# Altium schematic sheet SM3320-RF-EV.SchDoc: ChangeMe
size 469 x 254 mm; Date: Not shown in title block; ApprovedBy: Not shown in title block; CheckedBy: Not shown in title block; Author: Not shown in title block; CompanyName: Not shown in title block; DrawnBy: Not shown in title block; Engineer: Not shown in title block; Organization: Not shown in title block; Address1: Not shown in title block; Address2: Not shown in title block; Address3: Not shown in title block; Address4: Not shown in title block; DocumentNumber: 1; Revision: Use project parameter SCH_Rev; SheetNumber: 1; SheetTotal: 1; PageSetup: Record=PageOptions|CenterHorizontal=True|CenterVertical=True|PrintScale=0.85|XCorrection=0.00|YCorrection=0.00|PrintKind=2|BorderSize=5000000|LeftOffset=0|BottomOffset=0|Orientation=2|PaperLength=1000|PaperWidth=1000|Scale=100|PaperSource=15|PrintQuality=600|MediaType=1|DitherType=10|PaperKind=11x17|PrintScaleMode=0
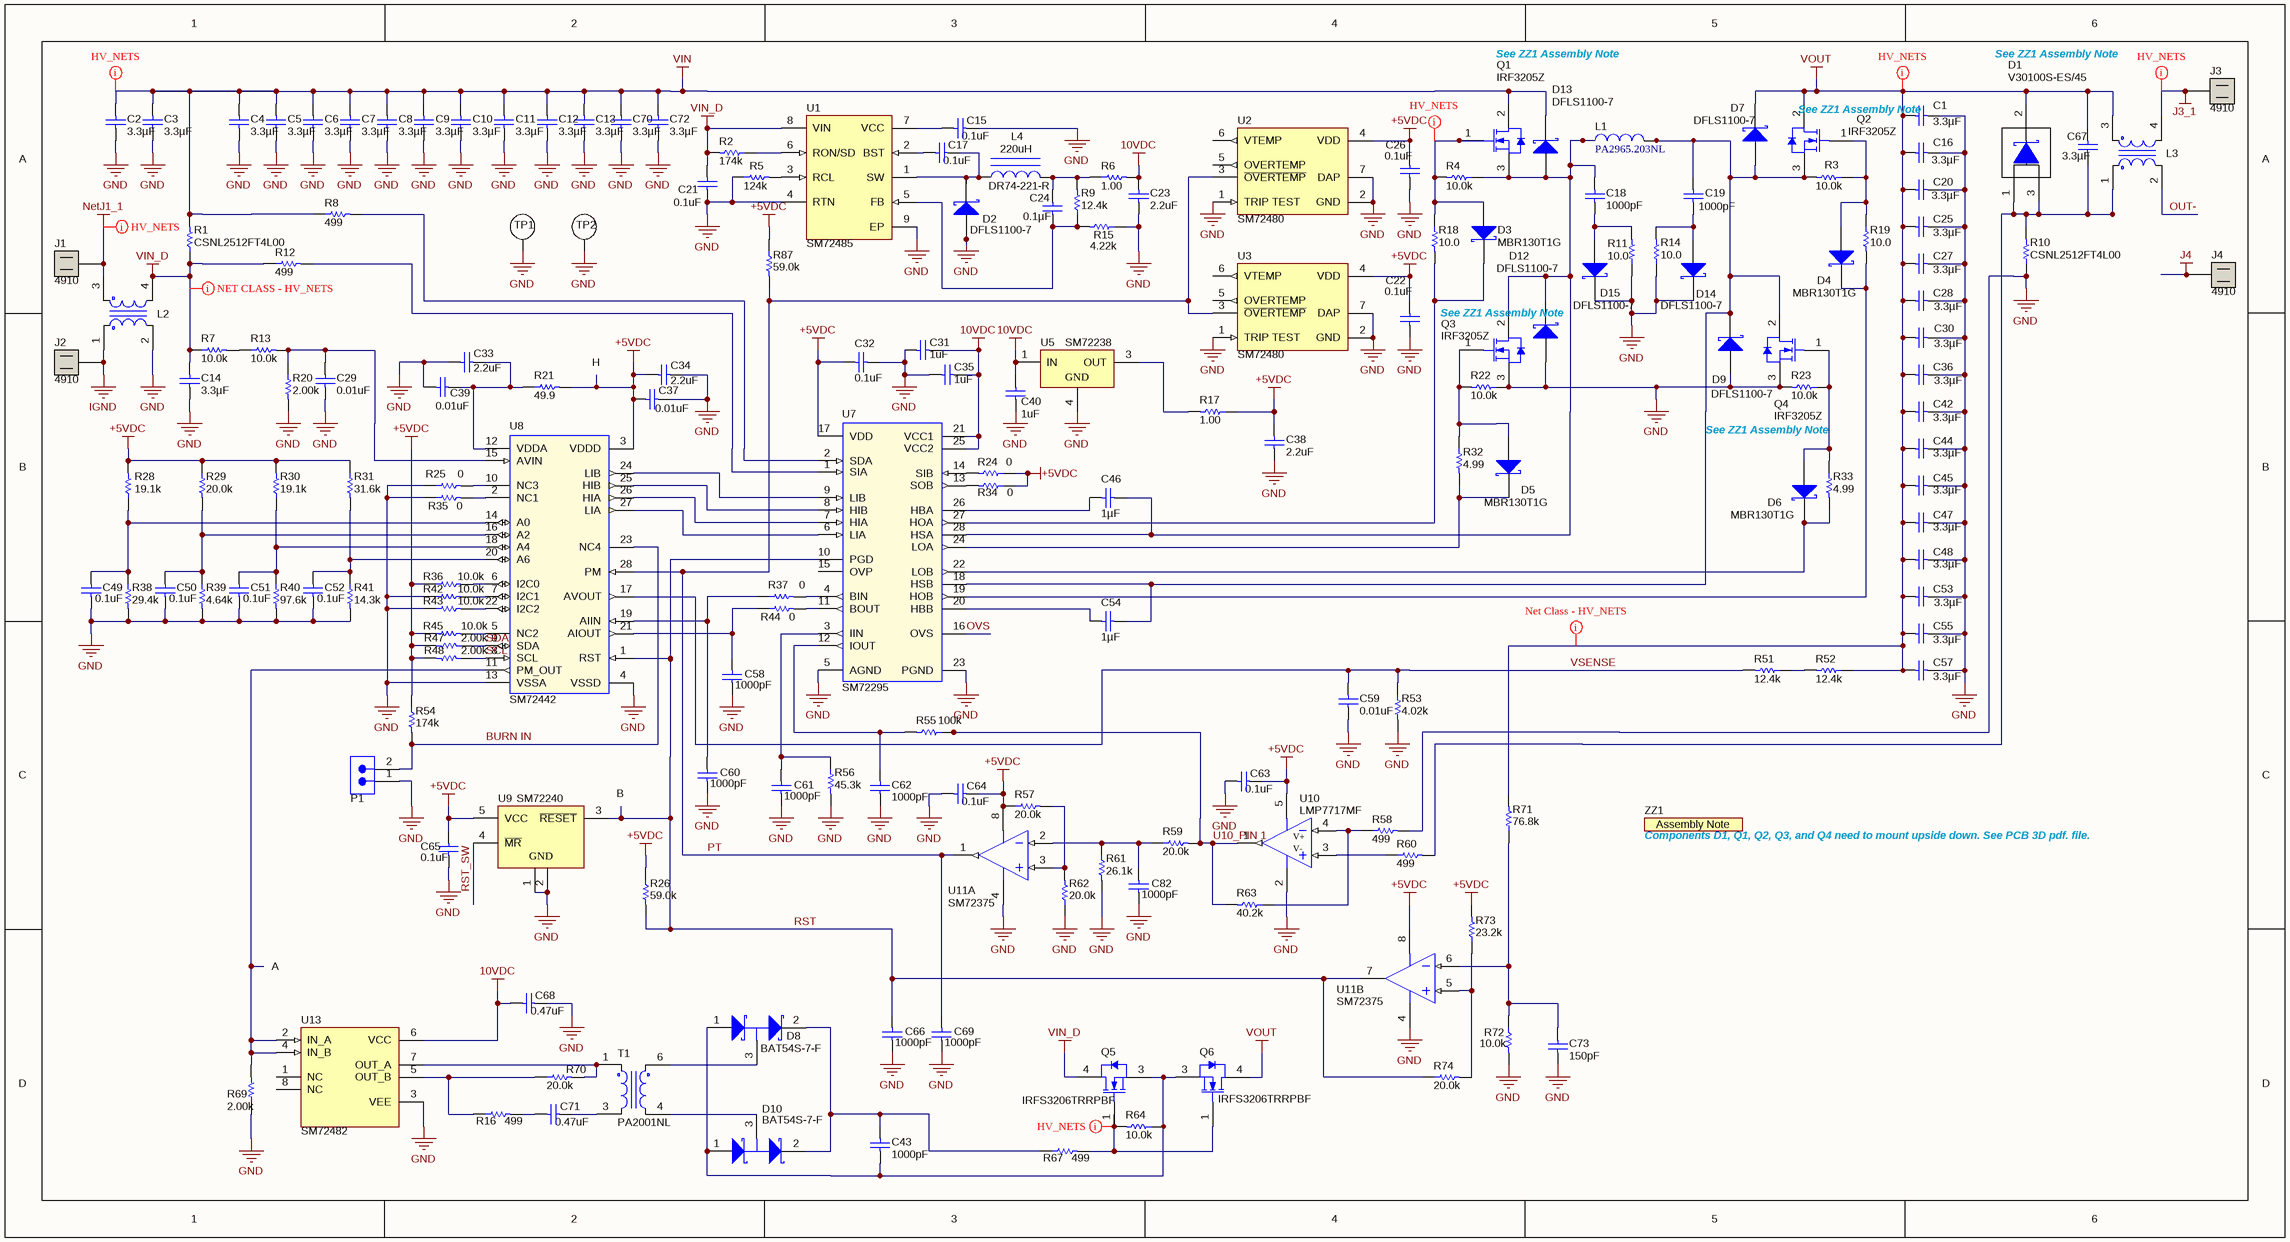
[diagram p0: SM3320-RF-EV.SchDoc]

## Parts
C1  ValueDisplayed: 3.3µF  [1210]  (hidden comment: C3225X7R1H335M)
C2  ValueDisplayed: 3.3µF  [1210]  (hidden comment: C3225X7R1H335M)
C3  ValueDisplayed: 3.3µF  [1210]  (hidden comment: C3225X7R1H335M)
C4  ValueDisplayed: 3.3µF  [1210]  (hidden comment: C3225X7R1H335M)
C5  ValueDisplayed: 3.3µF  [1210]  (hidden comment: C3225X7R1H335M)
C6  ValueDisplayed: 3.3µF  [1210]  (hidden comment: C3225X7R1H335M)
C7  ValueDisplayed: 3.3µF  [1210]  (hidden comment: C3225X7R1H335M)
C8  ValueDisplayed: 3.3µF  [1210]  (hidden comment: C3225X7R1H335M)
C9  ValueDisplayed: 3.3µF  [1210]  (hidden comment: C3225X7R1H335M)
C10  ValueDisplayed: 3.3µF  [1210]  (hidden comment: C3225X7R1H335M)
C11  ValueDisplayed: 3.3µF  [1210]  (hidden comment: C3225X7R1H335M)
C12  ValueDisplayed: 3.3µF  [1210]  (hidden comment: C3225X7R1H335M)
C13  ValueDisplayed: 3.3µF  [1210]  (hidden comment: C3225X7R1H335M)
C14  ValueDisplayed: 3.3µF  [1210]  (hidden comment: C3225X7R1H335M)
C15  value 0.1uF  [0603]  (hidden comment: GRM188R71E104KA01D)
C16  ValueDisplayed: 3.3µF  [1210]  (hidden comment: C3225X7R1H335M)
C17  value 0.1uF  [0603]  (hidden comment: GRM188R71E104KA01D)
C18  ValueDisplayed: 1000pF  [0805_HV]  (hidden comment: C0805C102K5RACTU)
C19  ValueDisplayed: 1000pF  [0805_HV]  (hidden comment: C0805C102K5RACTU)
C20  ValueDisplayed: 3.3µF  [1210]  (hidden comment: C3225X7R1H335M)
C21  value 0.1uF  [0805_HV]  (hidden comment: HMK212B7104KG-T)
C22  value 0.1uF  [0603]  (hidden comment: GRM188R71E104KA01D)
C23  value 2.2uF  [0805]  (hidden comment: EMK212B7225KG-T)
C24  ValueDisplayed: 0.1µF  [0603]  (hidden comment: GRM188R71E104KA01D)
C25  ValueDisplayed: 3.3µF  [1210]  (hidden comment: C3225X7R1H335M)
C26  value 0.1uF  [0603]  (hidden comment: GRM188R71E104KA01D)
C27  ValueDisplayed: 3.3µF  [1210]  (hidden comment: C3225X7R1H335M)
C28  ValueDisplayed: 3.3µF  [1210]  (hidden comment: C3225X7R1H335M)
C29  value 0.01uF  [0603]  (hidden comment: 06031C103MAT2A)
C30  ValueDisplayed: 3.3µF  [1210]  (hidden comment: C3225X7R1H335M)
C31  value 1uF  [0805]  (hidden comment: EMK212B7105KG-T)
C32  value 0.1uF  [0603]  (hidden comment: GRM188R71E104KA01D)
C33  value 2.2uF  [0805]  (hidden comment: EMK212B7225KG-T)
C34  value 2.2uF  [0805]  (hidden comment: EMK212B7225KG-T)
C35  value 1uF  [0805]  (hidden comment: EMK212B7105KG-T)
C36  ValueDisplayed: 3.3µF  [1210]  (hidden comment: C3225X7R1H335M)
C37  value 0.01uF  [0603]  (hidden comment: 06031C103MAT2A)
C38  value 2.2uF  [0805]  (hidden comment: EMK212B7225KG-T)
C39  value 0.01uF  [0603]  (hidden comment: 06031C103MAT2A)
C40  value 1uF  [0805]  (hidden comment: EMK212B7105KG-T)
C42  ValueDisplayed: 3.3µF  [1210]  (hidden comment: C3225X7R1H335M)
C43  ValueDisplayed: 1000pF  [0603]  (hidden comment: C1608C0G2A102J)
C44  ValueDisplayed: 3.3µF  [1210]  (hidden comment: C3225X7R1H335M)
C45  ValueDisplayed: 3.3µF  [1210]  (hidden comment: C3225X7R1H335M)
C46  ValueDisplayed: 1µF  [0805_HV]  (hidden comment: EMK212B7105KG-T)
C47  ValueDisplayed: 3.3µF  [1210]  (hidden comment: C3225X7R1H335M)
C48  ValueDisplayed: 3.3µF  [1210]  (hidden comment: C3225X7R1H335M)
C49  value 0.1uF  [0603]  (hidden comment: GRM188R71E104KA01D)
C50  value 0.1uF  [0603]  (hidden comment: GRM188R71E104KA01D)
C51  value 0.1uF  [0603]  (hidden comment: GRM188R71E104KA01D)
C52  value 0.1uF  [0603]  (hidden comment: GRM188R71E104KA01D)
C53  ValueDisplayed: 3.3µF  [1210]  (hidden comment: C3225X7R1H335M)
C54  ValueDisplayed: 1µF  [0805_HV]  (hidden comment: EMK212B7105KG-T)
C55  ValueDisplayed: 3.3µF  [1210]  (hidden comment: C3225X7R1H335M)
C57  ValueDisplayed: 3.3µF  [1210]  (hidden comment: C3225X7R1H335M)
C58  value 1000pF  [0603]  (hidden comment: C1608C0G2A102J)
C59  value 0.01uF  [0603]  (hidden comment: 06031C103MAT2A)
C60  value 1000pF  [0603]  (hidden comment: C1608C0G2A102J)
C61  value 1000pF  [0603]  (hidden comment: C1608C0G2A102J)
C62  value 1000pF  [0603]  (hidden comment: C1608C0G2A102J)
C63  value 0.1uF  [0603]  (hidden comment: GRM188R71E104KA01D)
C64  value 0.1uF  [0603]  (hidden comment: GRM188R71E104KA01D)
C65  value 0.1uF  [0603]  (hidden comment: GRM188R71E104KA01D)
C66  value 1000pF  [0603]  (hidden comment: C1608C0G2A102J)
C67  ValueDisplayed: 3.3µF  [1210]  (hidden comment: C3225X7R1H335M)
C68  value 0.47uF  [0805_HV]  (hidden comment: 0805YC474KAT2A)
C69  value 1000pF  [0603]  (hidden comment: C1608C0G2A102J)
C70  ValueDisplayed: 3.3µF  [1210]  (hidden comment: C3225X7R1H335M)
C71  value 0.47uF  [0805_HV]  (hidden comment: 0805YC474KAT2A)
C72  ValueDisplayed: 3.3µF  [1210]  (hidden comment: C3225X7R1H335M)
C73  ValueDisplayed: 150pF  [0603]  (hidden comment: C0603C151J5GACTU)
C82  value 1000pF  [0603]  (hidden comment: C1608C0G2A102J)
D1  V30100S-ES/45  [TO-220AB_HORIZONTAL]
D2  DFLS1100-7  [powerDI123]
D3  MBR130T1G  [SOD-123]
D4  MBR130T1G  [SOD-123]
D5  MBR130T1G  [SOD-123]
D6  MBR130T1G  [SOD-123]
D7  DFLS1100-7  [powerDI123]
D8  BAT54S-7-F  [SOT-23]
D9  DFLS1100-7  [powerDI123]
D10  BAT54S-7-F  [SOT-23]
D12  DFLS1100-7  [powerDI123]
D13  DFLS1100-7  [powerDI123]
D14  DFLS1100-7  [powerDI123]
D15  DFLS1100-7  [powerDI123]
J1  4910  [Keystone4910]
J2  4910  [Keystone4910]
J3  4910  [Keystone4910]
J4  4910  [Keystone4910]
L1  PA2965.203NL  [IND_EFD30C_DOT ON PIN 6]
L2  PA2972NL  [PA2972NL]  (value not drawn)
L3  PA2972NL  [PA2972NL]  (value not drawn)
L4  DR74-221-R  value 220uH  [DR74]
P1  TSW-102-07-T-S  [TSW-102-07-X-S]  (value not drawn)
Q1  IRF3205Z  [TO-220AB_HORIZONTAL]
Q2  IRF3205Z  [TO-220AB_HORIZONTAL]
Q3  IRF3205Z  [TO-220AB_HORIZONTAL]
Q4  IRF3205Z  [TO-220AB_HORIZONTAL]
Q5  IRFS3206TRRPBF  [DDPAK]
Q6  IRFS3206TRRPBF  [DDPAK]
R1  CSNL2512FT4L00  [2512M]
R2  value 174k  [0805_HV]  (hidden comment: CRCW0805174KFKEA)
R3  value 10.0k  [0603_HV]  (hidden comment: CRCW060310K0FKEA)
R4  value 10.0k  [0603_HV]  (hidden comment: CRCW060310K0FKEA)
R5  value 124k  [0603]  (hidden comment: CRCW0603124KFKEA)
R6  value 1.00  [0805]  (hidden comment: CRCW08051R00FNEA)
R7  value 10.0k  [1206]  (hidden comment: CRCW120610K0FKEA)
R8  value 499  [0603]  (hidden comment: CRCW0603499RFKEA)
R9  value 12.4k  [0603]  (hidden comment: CRCW060312K4FKEA)
R10  CSNL2512FT4L00  [2512M]
R11  value 10.0  [1218]  (hidden comment: CRCW121810R0FKEK)
R12  value 499  [0603]  (hidden comment: CRCW0603499RFKEA)
R13  value 10.0k  [1206]  (hidden comment: CRCW120610K0FKEA)
R14  value 10.0  [1218]  (hidden comment: CRCW121810R0FKEK)
R15  value 4.22k  [0603]  (hidden comment: CRCW06034K22FKEA)
R16  value 499  [0603]  (hidden comment: CRCW0603499RFKEA)
R17  value 1.00  [0603]  (hidden comment: CRCW06031R00FNEA)
R18  value 10.0  [0805_HV]  (hidden comment: CRCW080510R0FKEA)
R19  value 10.0  [0805_HV]  (hidden comment: CRCW080510R0FKEA)
R20  value 2.00k  [0603]  (hidden comment: CRCW06032K00FKEA)
R21  value 49.9  [0603]  (hidden comment: CRCW060349R9FKEA)
R22  value 10.0k  [0603]  (hidden comment: CRCW060310K0FKEA)
R23  value 10.0k  [0603]  (hidden comment: CRCW060310K0FKEA)
R24  value 0  [0603]  (hidden comment: CRCW06030000Z0EA)
R25  value 0  [0603]  (hidden comment: CRCW06030000Z0EA)
R26  value 59.0k  [0603]  (hidden comment: CRCW060359K0FKEA)
R28  value 19.1k  [0603]  (hidden comment: CRCW060319K1FKEA)
R29  value 20.0k  [0603]  (hidden comment: CRCW060320K0FKEA)
R30  value 19.1k  [0603]  (hidden comment: CRCW060319K1FKEA)
R31  value 31.6k  [0603]  (hidden comment: CRCW060331K6FKEA)
R32  value 4.99  [0805]  (hidden comment: CRCW08054R99FNEA)
R33  value 4.99  [0805]  (hidden comment: CRCW08054R99FNEA)
R34  value 0  [0603]  (hidden comment: CRCW06030000Z0EA)
R35  value 0  [0603]  (hidden comment: CRCW06030000Z0EA)
R36  value 10.0k  [0603]  (hidden comment: CRCW060310K0FKEA)
R37  value 0  [0603]  (hidden comment: CRCW06030000Z0EA)
R38  value 29.4k  [0603]  (hidden comment: CRCW060329K4FKEA)
R39  value 4.64k  [0603]  (hidden comment: CRCW06034K64FKEA)
R40  value 97.6k  [0603]  (hidden comment: CRCW060397K6FKEA)
R41  value 14.3k  [0603]  (hidden comment: CRCW060314K3FKEA)
R42  value 10.0k  [0603]  (hidden comment: CRCW060310K0FKEA)
R43  value 10.0k  [0603]  (hidden comment: CRCW060310K0FKEA)
R44  value 0  [0603]  (hidden comment: CRCW06030000Z0EA)
R45  value 10.0k  [0603]  (hidden comment: CRCW060310K0FKEA)
R47  value 2.00k  [0603]  (hidden comment: CRCW06032K00FKEA)
R48  value 2.00k  [0603]  (hidden comment: CRCW06032K00FKEA)
R51  value 12.4k  [1206]  (hidden comment: CRCW120612K4FKEA)
R52  value 12.4k  [1206]  (hidden comment: CRCW120612K4FKEA)
R53  value 4.02k  [0603]  (hidden comment: CRCW06034K02FKEA)
R54  value 174k  [0805_HV]  (hidden comment: CRCW0805174KFKEA)
R55  value 100k  [0603]  (hidden comment: CRCW0603100KFKEA)
R56  value 45.3k  [0603]  (hidden comment: CRCW060345K3FKEA)
R57  value 20.0k  [0603]  (hidden comment: CRCW060320K0FKEA)
R58  value 499  [0603]  (hidden comment: CRCW0603499RFKEA)
R59  value 20.0k  [0603]  (hidden comment: CRCW060320K0FKEA)
R60  value 499  [0603]  (hidden comment: CRCW0603499RFKEA)
R61  value 26.1k  [0603]  (hidden comment: CRCW060326K1FKEA)
R62  value 20.0k  [0603]  (hidden comment: CRCW060320K0FKEA)
R63  value 40.2k  [0603]  (hidden comment: CRCW060340K2FKEA)
R64  value 10.0k  [0603]  (hidden comment: CRCW060310K0FKEA)
R67  value 499  [0603]  (hidden comment: CRCW0603499RFKEA)
R69  value 2.00k  [0603]  (hidden comment: CRCW06032K00FKEA)
R70  value 20.0k  [0603]  (hidden comment: CRCW060320K0FKEA)
R71  value 76.8k  [0805_HV]  (hidden comment: CRCW080576K8FKEA)
R72  value 10.0k  [0603]  (hidden comment: CRCW060310K0FKEA)
R73  value 23.2k  [0603]  (hidden comment: CRCW060323K2FKEA)
R74  value 20.0k  [0603]  (hidden comment: CRCW060320K0FKEA)
R87  value 59.0k  [0603]  (hidden comment: CRCW060359K0FKEA)
T1  PA2001NL  [GT02-110-010_remove2and5]
TP1  5015  [Testpoint_Keystone_Miniature]  (value not drawn)
TP2  5015  [Testpoint_Keystone_Miniature]  (value not drawn)
U1  SM72485  [SDC08B]
U2  SM72480  [SDB06A]
U3  SM72480  [SDB06A]
U5  SM72238  [TD03B_N]
U7  SM72295  [M28B_M]
U8  SM72442  [MTC28_L]
U9  SM72240  [MF05A_L]
U10  LMP7717MF  [MF05A_M]
U11  SM72375  [MUA08A_M]  (parts A,B of 2)
U13  SM72482  [M08A_N]
ZZ1  Components D1, Q1, Q2, Q3, and Q4 need to mount upside down. See PCB 3D pdf. file.  [AssemblyNote]  (no BOM)

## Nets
10VDC: C23.1 C31.2 C35.2 C40.1 C68.2 R6.1 U5.1(IN) U7.21(VCC1) U7.25(VCC2) U13.6(VCC)
+5VDC: C22.2 C26.2 C32.1 C34.1 C37.2 C38.1 C63.1 C64.1 C65.2 R17.1 R21.1 R24.1 R26.1 R28.1 R29.1 R30.2 R31.1 R34.1 R36.2 R45.2 R47.2 R48.2 R54.1 R57.1 R73.1 R87.1 U2.4(VDD) U3.4(VDD) U7.17(VDD) U8.3(VDDD) U9.5(VCC) U10.5(V+) U11.8(V+)
GND: C1.2 C2.2 C3.2 C4.2 C5.2 C6.2 C7.2 C8.2 C9.2 C10.2 C11.2 C12.2 C13.2 C14.2 C15.1 C16.2 C20.2 C21.2 C22.1 C23.2 C25.2 C26.1 C27.2 C28.2 C29.2 C30.2 C31.1 C32.2 C33.1 C34.2 C35.1 C36.2 C37.1 C38.2 C39.2 C40.2 C42.2 C44.2 C45.2 C47.2 C48.2 C49.2 C50.2 C51.2 C52.2 C53.2 C55.2 C57.2 C58.2 C59.2 C60.2 C61.2 C62.2 C63.2 C64.2 C65.1 C66.2 C68.1 C69.2 C70.2 C72.2 C73.2 C82.2 D2.1(A) D9.1(A) D12.1(A) D14.2(K) D15.2(K) L2.2 P1.1 Q3.3(S) Q4.3(S) R5.2 R10.1 R11.1 R14.1 R15.2 R20.1 R22.2 R23.1 R25.2 R35.2 R38.2 R39.2 R40.2 R41.2 R42.2 R43.2 R53.2 R56.2 R58.2 R61.2 R62.1 R69.2 R72.1 TP1.1 TP2.1 U1.4(RTN) U1.9(EP) U2.1(TRIP_TEST) U2.2(GND) U2.7(DAP) U3.1(TRIP_TEST) U3.2(GND) U3.7(DAP) U5.4(GND) U7.5(AGND) U7.23(PGND) U8.4(VSSD) U8.13(VSSA) U9.1(GND) U9.2(GND) U10.2(V-) U11.4(V-) U13.3(VEE)
IGND: J2.1 L2.1
J3_1: J3.1 L3.4
J4: J4.1
NetJ1_1: J1.1 L2.3
VIN: C2.1 C3.1 C4.1 C5.1 C6.1 C7.1 C8.1 C9.1 C10.1 C11.1 C12.1 C13.1 C70.1 C72.1 D13.2(K) Q1.2(D) R1.2 R8.2
VIN_D: C14.1 C21.1 L2.4 Q5.4(D) R1.1 R2.2 R7.1 R12.2 U1.8(VIN)
VOUT: C1.1 C16.1 C20.1 C25.1 C27.1 C28.1 C30.1 C36.1 C42.1 C44.1 C45.1 C47.1 C48.1 C53.1 C55.1 C57.1 C67.1 D1.2(K) D7.2(K) L3.3 Q2.2(D) Q6.4(D) R52.1 R71.2
BURN IN: P1.2 R54.2 U8.23(NC4)
OUT-: L3.2
OVS: U7.16(OVS)
PT: C69.1 R87.2 U2.3(~{OVERTEMP}) U3.3(~{OVERTEMP}) U8.28(PM) U11.1(OUTA)
RST: C66.1 R26.2 R74.2 U7.10(PGD) U8.1(RST) U9.3(~{RESET}) U11.7(OUTB)
RST_SW: U9.4(~{MR})
SCL: R48.1 U8.8(SCL)
SDA: R47.1 U8.9(SDA)
U10_PIN 1: R55.1 R59.2 R63.2 U10.1(OUT)
VSENSE: C59.1 R51.2 R53.1 U8.17(AVOUT)
NetC15_2: C15.2 U1.7(VCC)
NetC17_1: C17.1 D2.2(K) L4.1 U1.1(SW)
NetC17_2: C17.2 U1.2(BST)
NetC18_1: C18.1 C46.1 D12.2(K) D13.1(A) L1.1 L1.2 L1.3 L1.4 L1.5 L1.6 Q1.3(S) Q3.2(D) R4.2 U7.28(HSA)
NetC18_2: C18.2 D15.1(A) R11.2
NetC19_1: C19.1 C54.1 D7.1(A) D9.2(K) L1.7 L1.8 L1.9 L1.10 L1.11 L1.12 Q2.3(S) Q4.2(D) R3.1 U7.18(HSB)
NetC19_2: C19.2 D14.1(A) R14.2
NetC24_1: C24.1 L4.2 R6.2 R9.1
NetC24_2: C24.2 R9.2 R15.1 U1.5(FB)
NetC29_1: C29.1 R13.2 R20.2 U8.15(AVIN)
NetC33_2: C33.2 C39.1 R21.2 U8.12(VDDA)
NetC43_1: C43.1 D8.2(K) D10.2(K) R67.2
NetC43_2: C43.2 D8.1(A) D10.1(A) Q5.3(S) Q6.3(S) R64.2
NetC46_2: C46.2 U7.26(HBA)
NetC49_1: C49.1 R28.2 R38.1 U8.14(A0)
NetC50_1: C50.1 R29.2 R39.1 U8.16(A2)
NetC51_1: C51.1 R30.1 R40.1 U8.18(A4)
NetC52_1: C52.1 R31.2 R41.1 U8.20(A6)
NetC54_2: C54.2 U7.20(HBB)
NetC58_1: C58.1 R44.2 U8.21(AIOUT)
NetC60_1: C60.1 R37.2 U8.19(AIIN)
NetC61_1: C61.1 R56.1 U7.3(IIN)
NetC62_1: C62.1 R55.2 U7.12(IOUT)
NetC67_2: C67.2 D1.1(A) D1.3(A) L3.1 R10.2 R60.2
NetC71_1: C71.1 T1.3
NetC71_2: C71.2 R16.1
NetC73_1: C73.1 R71.1 R72.2 U11.6(INB-)
NetC82_1: C82.1 R59.1 R61.1 U11.2(INA-)
NetD3_1: D3.1(A) Q1.1(G) R4.1 R18.1
NetD3_2: D3.2(K) R18.2 U7.27(HOA)
NetD4_1: D4.1(A) Q2.1(G) R3.2 R19.1
NetD4_2: D4.2(K) R19.2 U7.19(HOB)
NetD5_1: D5.1(A) Q3.1(G) R22.1 R32.1
NetD5_2: D5.2(K) R32.2 U7.24(LOA)
NetD6_1: D6.1(A) Q4.1(G) R23.2 R33.1
NetD6_2: D6.2(K) R33.2 U7.22(LOB)
NetD8_3: D8.3(C) T1.6
NetD10_3: D10.3(C) T1.4
NetQ5_1: Q5.1(G) Q6.1(G) R64.1 R67.1
NetR2_1: R2.1 U1.6(RON/SD)
NetR5_1: R5.1 U1.3(RCL)
NetR7_2: R7.2 R13.1
NetR8_1: R8.1 U7.2(SDA)
NetR12_1: R12.1 U7.1(SIA)
NetR16_2: R16.2 R70.1 U13.5(OUT_B)
NetR17_2: R17.2 U5.3(OUT)
NetR24_2: R24.2 U7.14(SIB)
NetR25_1: R25.1 U8.10(NC3)
NetR34_2: R34.2 U7.13(SOB)
NetR35_1: R35.1 U8.2(NC1)
NetR36_1: R36.1 U8.6(I2C0)
NetR37_1: R37.1 U7.4(BIN)
NetR42_1: R42.1 U8.7(I2C1)
NetR43_1: R43.1 U8.22(I2C2)
NetR44_1: R44.1 U7.11(BOUT)
NetR45_1: R45.1 U8.5(NC2)
NetR51_1: R51.1 R52.2
NetR57_2: R57.2 R62.2 U11.3(INA+)
NetR58_1: R58.1 R63.1 U10.4(IN-)
NetR60_1: R60.1 U10.3(IN+)
NetR69_1: R69.1 U8.11(PM_OUT) U13.2(IN_A) U13.4(IN_B)
NetR70_2: R70.2 T1.1 U13.7(OUT_A)
NetR73_2: R73.2 R74.1 U11.5(INB+)
NetU7_6: U7.6(LIA) U8.27(LIA)
NetU7_7: U7.7(HIA) U8.26(HIA)
NetU7_8: U7.8(HIB) U8.25(HIB)
NetU7_9: U7.9(LIB) U8.24(LIB)

Not connected (* = marked no-connect by the designer): U2 5(OVERTEMP) 6(VTEMP); U3 5(OVERTEMP) 6(VTEMP); U7 15(OVP); U13 1(NC) 8(NC)

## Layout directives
net class HV_NETS: J3_1, NetD3_1, NetJ1_1, NetQ5_1, VIN, VIN_D, VOUT

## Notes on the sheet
- See ZZ1 Assembly Note
- (near C1) See ZZ1 Assembly Note
- (near D12) See ZZ1 Assembly Note
- H
- (near U9) B
- A

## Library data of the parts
C1-C14 C16 C20 C25 C27 C28 C30 C36 C42 C44 C45 C47 C48 C53 C55 C57 C67 C70 C72 = C3225X7R1H335M: CAP, CERM, 3.3uF, 50V, +/-20%, X7R, 1210; Manufacturer: TDK; Polarized: N; TaMax_C: 125; TaMin_C: -55; Tolerance_%: 20; VDC_V: 50; Cap_F: 3.3E-6; CompType: Capacitor
C15 C17 C22 C26 C32 C49-C52 C63-C65 = GRM188R71E104KA01D: CAP, CERM, 0.1uF, 25V, +/-10%, X7R, 0603; Manufacturer: MuRata; Polarized: N; TaMax_C: 125; TaMin_C: -55; Tolerance_%: 10; VDC_V: 25; Cap_F: 100.0E-9; CompType: Capacitor; ValueDisplayed: 0.1µF
C18 C19 = C0805C102K5RACTU: CAP, CERM, 1000pF, 50V, +/-10%, X7R, 0805; Manufacturer: Kemet; Cap_Case: 0805; ESR_Ohm: 0.384; IRMS_A: 0.214; Polarized: N; TaMax_C: 125; TaMin_C: -55; Tolerance_%: 10; VDC_V: 50; Cap_F: 1.0E-9; CompType: Capacitor; Value1: 0.384 ohm
C21 = HMK212B7104KG-T: CAP, CERM, 0.1uF, 100V, +/-10%, X7R, 0805; Manufacturer: Taiyo Yuden; Cap_Case: 0805; Polarized: N; TaMax_C: 125; TaMin_C: -55; Tolerance_%: 10; VDC_V: 100; Cap_F: 100.0E-9; CompType: Capacitor; ValueDisplayed: 0.1µF
C23 C33 C34 C38 = EMK212B7225KG-T: CAP, CERM, 2.2uF, 16V, +/-10%, X7R, 0805; Manufacturer: Taiyo Yuden; Polarized: N; TaMax_C: 125; TaMin_C: -55; Tolerance_%: 10; VDC_V: 16; Cap_F: 2.2E-6; CompType: Capacitor; ValueDisplayed: 2.2µF
C24 = GRM188R71E104KA01D: CAP, CERM, 0.1uF, 25V, +/-10%, X7R, 0603; Manufacturer: MuRata; Polarized: N; TaMax_C: 125; TaMin_C: -55; Tolerance_%: 10; VDC_V: 25; Cap_F: 100.0E-9; CompType: Capacitor
C29 C37 C39 C59 = 06031C103MAT2A: CAP, CERM, 0.01uF, 100V, +/-20%, X7R, 0603; Manufacturer: AVX; ESR_Ohm: 0.098; Polarized: N; TaMax_C: 125; TaMin_C: -55; Tolerance_%: 20; VDC_V: 100; Cap_F: 10.0E-9; CompType: Capacitor; Value1: 0.098 ohm; ValueDisplayed: 0.01µF
C31 C35 C40 = EMK212B7105KG-T: CAP, CERM, 1uF, 16V, +/-10%, X7R, 0805; Manufacturer: Taiyo Yuden; Polarized: N; TaMax_C: 125; TaMin_C: -55; Tolerance_%: 10; VDC_V: 16; Cap_F: 1.0E-6; CompType: Capacitor; ValueDisplayed: 1µF
C43 C58 C60-C62 C66 C69 C82 = C1608C0G2A102J: CAP, CERM, 1000pF, 100V, +/-5%, C0G/NP0, 0603; Manufacturer: TDK; ESR_Ohm: 0.0589; Polarized: N; TaMax_C: 125; TaMin_C: -55; Tolerance_%: 5; VDC_V: 100; Cap_F: 1.0E-9; CompType: Capacitor; Value1: 0.0589 ohm
C46 C54 = EMK212B7105KG-T: CAP, CERM, 1uF, 16V, +/-10%, X7R, 0805; Manufacturer: Taiyo Yuden; Cap_Case: 0805; Polarized: N; TaMax_C: 125; TaMin_C: -55; Tolerance_%: 10; VDC_V: 16; Cap_F: 1.0E-6; CompType: Capacitor
C68 C71 = 0805YC474KAT2A: CAP, CERM, 0.47uF, 16V, +/-10%, X7R, 0805; Manufacturer: AVX; Cap_Case: 0805; ESR_Ohm: 0.011; Polarized: N; TaMax_C: 125; TaMin_C: -55; Tolerance_%: 10; VDC_V: 16; Cap_F: 470.0E-9; CompType: Capacitor; Value1: 0.011 ohm; ValueDisplayed: 0.47µF
C73 = C0603C151J5GACTU: CAP, CERM, 150pF, 50V, +/-5%, C0G/NP0, 0603; Manufacturer: Kemet; Polarized: N; TaMax_C: 125; TaMin_C: -55; Tolerance_%: 5; VDC_V: 50; Cap_F: 150.0E-12; CompType: Capacitor
D1 = V30100S-E3/4W: DIODE SCHOTTKY 30A 100V TO-220AB; Manufacturer: Vishay-Semiconductor; Io_A: 30
D2 D7 D9 D12-D15 = DFLS1100-7: Diode, Schottky, 100V, 1A, PowerDI123; Manufacturer: Diodes Inc.; RJC_CperW: 7; Vf_V: 0.77; Io_A: 1; Vr_V: 100; TJMax_C: 175; Value: 0.77V
D3-D6 = MBR130T1G: Diode, Schottky, 30V, 1A, SOD-123; Manufacturer: ON Semiconductor; RJC_CperW: 108; Vf_V: 0.47; Io_A: 1; Vr_V: 30; TJMax_C: 125; Value: 0.47V
D8 D10 = BAT54S-7-F: Diode, Schottky, 30V, 0.2A, SOT-23; Manufacturer: Diodes Inc.; Value: 0.65V; Vf_V: 0.65; Io_A: 0.2; Vr_V: 30; TJmax_C: 125
J1-J4 = 4910: PC Quick-Fit 0.250 Horizontal Tab; Manufacturer: Keystone Electronics; CompType: Quick-Fit Tab; SymbolCreator: codlsc; U/M: EA
L1 = PA2965.203NL: Inductor 27uH EFD-30 core; Manufacturer: Pulse Electronics; Ind_H: 0.000027
L2 L3 = PA2972NL: Choke Filter; Manufacturer: Pulse; CompType: Inductor; SymbolVersion: 2010 -08-19; SymbolCreator: cdnlsc
L4 = DR74-221-R: Inductor, Shielded Drum Core, Ferrite, 220uH, 0.56A, 0.907 ohm, SMD; Manufacturer: Coiltronics; Ind_H: 220.0E-6; DCR_Ohm: 0.907; Imax_A: 0.56; Irms: 0.56A @ 40C rise; Isat: 0.66A @ 30% inductance drop; U/M: EA; ValueDisplayed: 220µH
P1 = TSW-102-07-T-S: Header, TH, 100mil, 1x2, Tin plated, 230 mil above insulator; Manufacturer: Samtec Inc.
Q1-Q4 = IRF3205Z: MOSFET 55V 6.5 mOHM T0-220AB; Manufacturer: International Rectifier; SymbolVersion: 2010 - 08 -24; CompType: tRANSISTOR; SymbolCreator: cdnlsc
Q5 Q6 = IRFS3206TRRPBF: MOSFET N-CH 60V 120A D2PAK; Manufacturer: International Rectifier; SymbolVersion: 2010 - 08 - 24; SymbolCreator: cdnlsc
R1 R10 = CSNL2512FT4L00: RES .004 OHM 2W 1% 2512 SMD; Manufacturer: Stackpole Electronics Inc; CompType: Used in some BOM reports.  Useful for finding later.; SymbolVersion: 2010 - 08 - 24; SymbolCreator: cdnlsc
R2 R54 = CRCW0805174KFKEA: RES, 174k ohm, 1%, 0.125W, 0805; Manufacturer: Vishay-Dale; CompType: Resistor; Tolerance_%: 1; VDC_V: 150; Power_W: 0.125; Res_Ohm: 174000; EIA_Code: E96
R3 R4 R72 = CRCW060310k0FKEA: RES, 10.0k ohm, 1%, 0.1W, 0603; Manufacturer: Vishay-Dale; CompType: Resistor; Tolerance_%: 1; VDC_V: 75; Power_W: 0.1; Res_Ohm: 10000; Value_Code: 10k0; EIA_Code: E96
R5 = CRCW0603124kFKEA: RES, 124k ohm, 1%, 0.1W, 0603; Manufacturer: Vishay-Dale; CompType: Resistor; Tolerance_%: 1; VDC_V: 75; Power_W: 0.1; Res_Ohm: 124000; EIA_Code: E96
R6 = CRCW08051R00FNEA: RES, 1.00 ohm, 1%, 0.125W, 0805; Manufacturer: Vishay-Dale; CompType: Resistor; Tolerance_%: 1; VDC_V: 150; Power_W: 0.125; Value_Code: 1R00; EIA_Code: E96
R7 R13 = CRCW120610K0FKEA: RES, 10.0k ohm, 1%, 0.25W, 1206; Manufacturer: Vishay-Dale; CompType: Resistor; Tolerance_%: 1; VDC_V: 200; Power_W: 0.25; Res_Ohm: 10000; Value_Code: 10k0; EIA_Code: E96
R8 R12 R16 R58 R60 R67 = CRCW0603499RFKEA: RES, 499 ohm, 1%, 0.1W, 0603; Manufacturer: Vishay-Dale; CompType: Resistor; Tolerance_%: 1; VDC_V: 75; Power_W: 0.1; Value_Code: 499R; EIA_Code: E96
R9 = CRCW060312K4FKEA: RES, 12.4k ohm, 1%, 0.1W, 0603; Manufacturer: Vishay-Dale; CompType: Resistor; Tolerance_%: 1; VDC_V: 75; Power_W: 0.1; Res_Ohm: 12400; Value_Code: 12k4; EIA_Code: E96
R11 R14 = CRCW121810R0FKEK: RES, 10.0 ohm, 1%, 1W, 1218 SMD; Manufacturer: Vishay-Dale; CompType: Resistor; Tolerance_%: 1; VDC_V: 200; Res_Ohm: 10; Value_Code: 10R0; EIA_Code: E96
R15 = CRCW06034k22FKEA: RES, 4.22k ohm, 1%, 0.1W, 0603; Manufacturer: Vishay-Dale; CompType: Resistor; Tolerance_%: 1; VDC_V: 75; Power_W: 0.1; Res_Ohm: 4220; Value_Code: 4k22; EIA_Code: E96
R17 = CRCW06031R00FNEA: RES, 1.00 ohm, 1%, 0.1W, 0603; Manufacturer: Vishay-Dale; CompType: Resistor; Tolerance_%: 1; VDC_V: 75; Power_W: 0.1; Value_Code: 1R00; EIA_Code: E96
R18 R19 = CRCW080510R0FKEA: RES, 10.0 ohm, 1%, 0.125W, 0805; Manufacturer: Vishay-Dale; CompType: Resistor; Tolerance_%: 1; VDC_V: 150; Power_W: 0.125; Res_Ohm: 10; Value_Code: 10R0; EIA_Code: E96
R20 R47 R48 R69 = CRCW06032K00FKEA: RES, 2.00k ohm, 1%, 0.1W, 0603; Manufacturer: Vishay-Dale; CompType: Resistor; Tolerance_%: 1; VDC_V: 75; Power_W: 0.1; Res_Ohm: 2000; Value_Code: 2k00; EIA_Code: E96
R21 = CRCW060349R9FKEA: RES, 49.9 ohm, 1%, 0.1W, 0603; Manufacturer: Vishay-Dale; CompType: Resistor; Tolerance_%: 1; VDC_V: 75; Power_W: 0.1; Value_Code: 49R9; EIA_Code: E96
R22 R23 R36 R42 R43 R45 R64 = CRCW060310K0FKEA: RES, 10.0k ohm, 1%, 0.1W, 0603; Manufacturer: Vishay-Dale; CompType: Resistor; Tolerance_%: 1; VDC_V: 75; Power_W: 0.1; Res_Ohm: 10000; Value_Code: 10k0; EIA_Code: E96
R24 R25 R34 R35 R37 R44 = CRCW06030000Z0EA: RES, 0 ohm, 5%, 0.1W, 0603; Manufacturer: Vishay-Dale; CompType: Resistor; Tolerance_%: 5; VDC_V: 75; Power_W: 0.1; Value_Code: 0000; EIA_Code: E24
R26 R87 = CRCW060359K0FKEA: RES, 59.0k ohm, 1%, 0.1W, 0603; Manufacturer: Vishay-Dale; CompType: Resistor; Tolerance_%: 1; VDC_V: 75; Power_W: 0.1; Res_Ohm: 59000; Value_Code: 59k0; EIA_Code: E96
R28 R30 = CRCW060319K1FKEA: RES, 19.1k ohm, 1%, 0.1W, 0603; Manufacturer: Vishay-Dale; CompType: Resistor; Tolerance_%: 1; VDC_V: 75; Power_W: 0.1; Res_Ohm: 19100; Value_Code: 19k1; EIA_Code: E96
R29 R57 R59 R62 R70 R74 = CRCW060320K0FKEA: RES, 20.0k ohm, 1%, 0.1W, 0603; Manufacturer: Vishay-Dale; CompType: Resistor; Tolerance_%: 1; VDC_V: 75; Power_W: 0.1; Res_Ohm: 20000; Value_Code: 20k0; EIA_Code: E96
R31 = CRCW060331K6FKEA: RES, 31.6k ohm, 1%, 0.1W, 0603; Manufacturer: Vishay-Dale; CompType: Resistor; Tolerance_%: 1; VDC_V: 75; Power_W: 0.1; Res_Ohm: 31600; Value_Code: 31k6; EIA_Code: E96
R32 R33 = CRCW08054R99FNEA: RES, 4.99 ohm, 1%, 0.125W, 0805; Manufacturer: Vishay-Dale; CompType: Resistor; Tolerance_%: 1; VDC_V: 150; Power_W: 0.125; Value_Code: 4R99; EIA_Code: E96
R38 = CRCW060329K4FKEA: RES, 29.4k ohm, 1%, 0.1W, 0603; Manufacturer: Vishay-Dale; CompType: Resistor; Tolerance_%: 1; VDC_V: 75; Power_W: 0.1; Res_Ohm: 29400; Value_Code: 29k4; EIA_Code: E96
R39 = CRCW06034K64FKEA: RES, 4.64k ohm, 1%, 0.1W, 0603; Manufacturer: Vishay-Dale; CompType: Resistor; Tolerance_%: 1; VDC_V: 75; Power_W: 0.1; Res_Ohm: 4640; Value_Code: 4k64; EIA_Code: E96
R40 = CRCW060397K6FKEA: RES, 97.6k ohm, 1%, 0.1W, 0603; Manufacturer: Vishay-Dale; CompType: Resistor; Tolerance_%: 1; VDC_V: 75; Power_W: 0.1; Res_Ohm: 97600; Value_Code: 97k6; EIA_Code: E96
R41 = CRCW060314K3FKEA: RES, 14.3k ohm, 1%, 0.1W, 0603; Manufacturer: Vishay-Dale; CompType: Resistor; Tolerance_%: 1; VDC_V: 75; Power_W: 0.1; Res_Ohm: 14300; Value_Code: 14k3; EIA_Code: E96
R51 R52 = CRCW120612K4FKEA: RES, 12.4k ohm, 1%, 0.25W, 1206; Manufacturer: Vishay-Dale; CompType: Resistor; Tolerance_%: 1; VDC_V: 200; Power_W: 0.25; Res_Ohm: 12400; Value_Code: 12k4; EIA_Code: E96
R53 = CRCW06034K02FKEA: RES, 4.02k ohm, 1%, 0.1W, 0603; Manufacturer: Vishay-Dale; CompType: Resistor; Tolerance_%: 1; VDC_V: 75; Power_W: 0.1; Res_Ohm: 4020; Value_Code: 4k02; EIA_Code: E96
R55 = CRCW0603100KFKEA: RES, 100k ohm, 1%, 0.1W, 0603; Manufacturer: Vishay-Dale; CompType: Resistor; Tolerance_%: 1; VDC_V: 75; Power_W: 0.1; Res_Ohm: 100000; EIA_Code: E96
R56 = CRCW060345K3FKEA: RES, 45.3k ohm, 1%, 0.1W, 0603; Manufacturer: Vishay-Dale; CompType: Resistor; Tolerance_%: 1; VDC_V: 75; Power_W: 0.1; Res_Ohm: 45300; Value_Code: 45k3; EIA_Code: E96
R61 = CRCW060326K1FKEA: RES, 26.1k ohm, 1%, 0.1W, 0603; Manufacturer: Vishay-Dale; CompType: Resistor; Tolerance_%: 1; VDC_V: 75; Power_W: 0.1; Res_Ohm: 26100; Value_Code: 26k1; EIA_Code: E96
R63 = CRCW060340K2FKEA: RES, 40.2k ohm, 1%, 0.1W, 0603; Manufacturer: Vishay-Dale; CompType: Resistor; Tolerance_%: 1; VDC_V: 75; Power_W: 0.1; Res_Ohm: 40200; Value_Code: 40k2; EIA_Code: E96
R71 = CRCW080576K8FKEA: RES, 76.8k ohm, 1%, 0.125W, 0805; Manufacturer: Vishay-Dale; CompType: Resistor; Tolerance_%: 1; VDC_V: 150; Power_W: 0.125; Res_Ohm: 76800; Value_Code: 76k8; EIA_Code: E96
R73 = CRCW060323k2FKEA: RES, 23.2k ohm, 1%, 0.1W, 0603; Manufacturer: Vishay-Dale; CompType: Resistor; Tolerance_%: 1; VDC_V: 75; Power_W: 0.1; Res_Ohm: 23200; Value_Code: 23k2; EIA_Code: E96
T1 = PA2001NL: SMT GATE TRANS 1:1 1500V 403 uH 0.60R; Manufacturer: Pulse; CompType: Transformer; SymbolVersion: 2010 - 08 -24; SymbolCreator: cdnlsc
TP1 TP2 = 5015: Test Point, SMT, Miniature; Manufacturer: Keystone Electronics; CompType: Test Point Loop
U1 = SM72485: 100V, 150 mA Constant On-Time Buck Switching Regulator; Manufacturer: National Semiconductor; CompType: Switcher; PackageTopMarking: S2485
U2 U3 = SM72480: 1.6V, LLP-6 Factory Preset Temperature Switch and Temperature Sensor; Manufacturer: National Semiconductor; CompType: Temp Sensor IC; PackageTopMarking: S80
U5 = SM72238: 5V Micropower Voltage Regulator; Manufacturer: National Semiconductor; CompType: LDO; PackageTopMarking: S72238
U7 = SM72295: Photovoltaic Full Bridge Driver; Manufacturer: National Semiconductor; PackageTopMarking: S13051
U8 = SM72442: Programmable Maximum Power Point Tracking Controller for Photovoltaic Solar Panels; Manufacturer: National Semiconductor; CompType: MPPT Controller; PackageTopMarking: S02442
U9 = SM72240: 5-Pin Microprocessor Reset Circuits; Manufacturer: National Semiconductor; CompType: Supervisory Circuit Monitors; PackageTopMarking: 2240
U10 = LMP7717MF: 1.8V Precision, Decompensated Single Low Noise CMOS Input Op Amp; Manufacturer: National Semiconductor; Characteristics: LMP7717MF 1.8V Precision, Decompensated Single Low Noise CMOS Input Op Amp; CompType: OpAmp IC; TaMin_C: -40.0; TaMax_C: 125.0; PowerWise: Y
U11 = SM72375: Dual Micropower Rail-To-Rail Input CMOS Comparator with Open Drain Output; Manufacturer: National Semiconductor; PackageTopMarking: S375
U13 = SM72482: Dual 5A Compound Gate Driver; Manufacturer: National Semiconductor; CompType: Switcher; PackageTopMarking: S482
ZZ1 = Assembly Note: SymbolCreator: codlsc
